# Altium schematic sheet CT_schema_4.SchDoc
size 511 x 398 mm
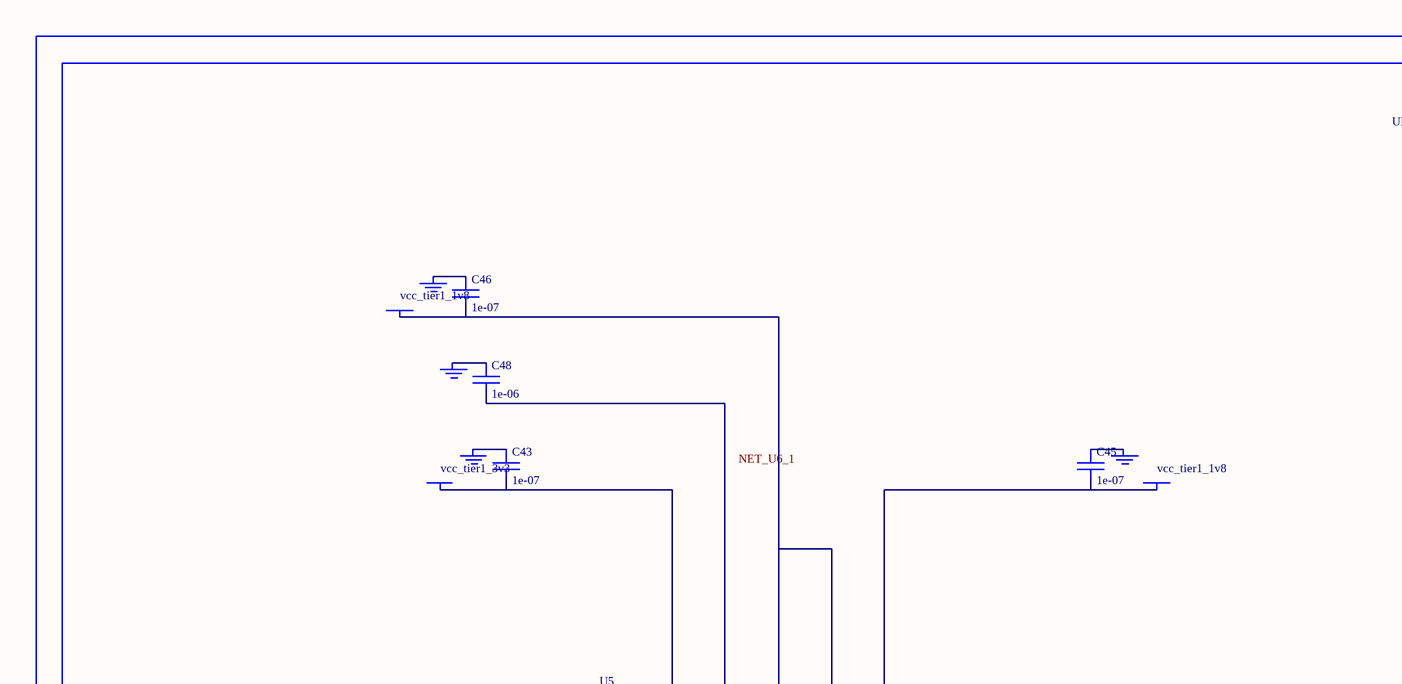
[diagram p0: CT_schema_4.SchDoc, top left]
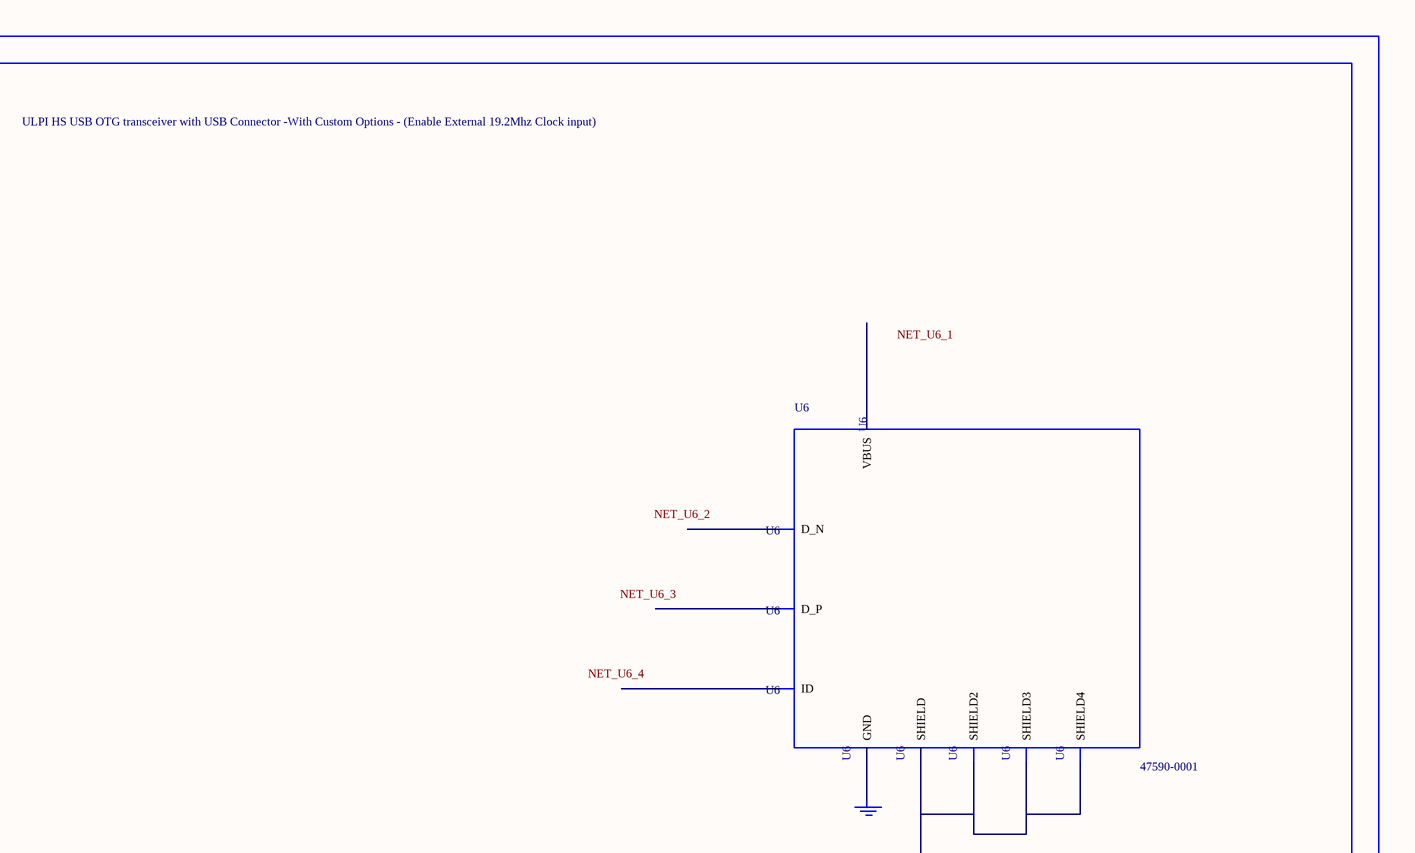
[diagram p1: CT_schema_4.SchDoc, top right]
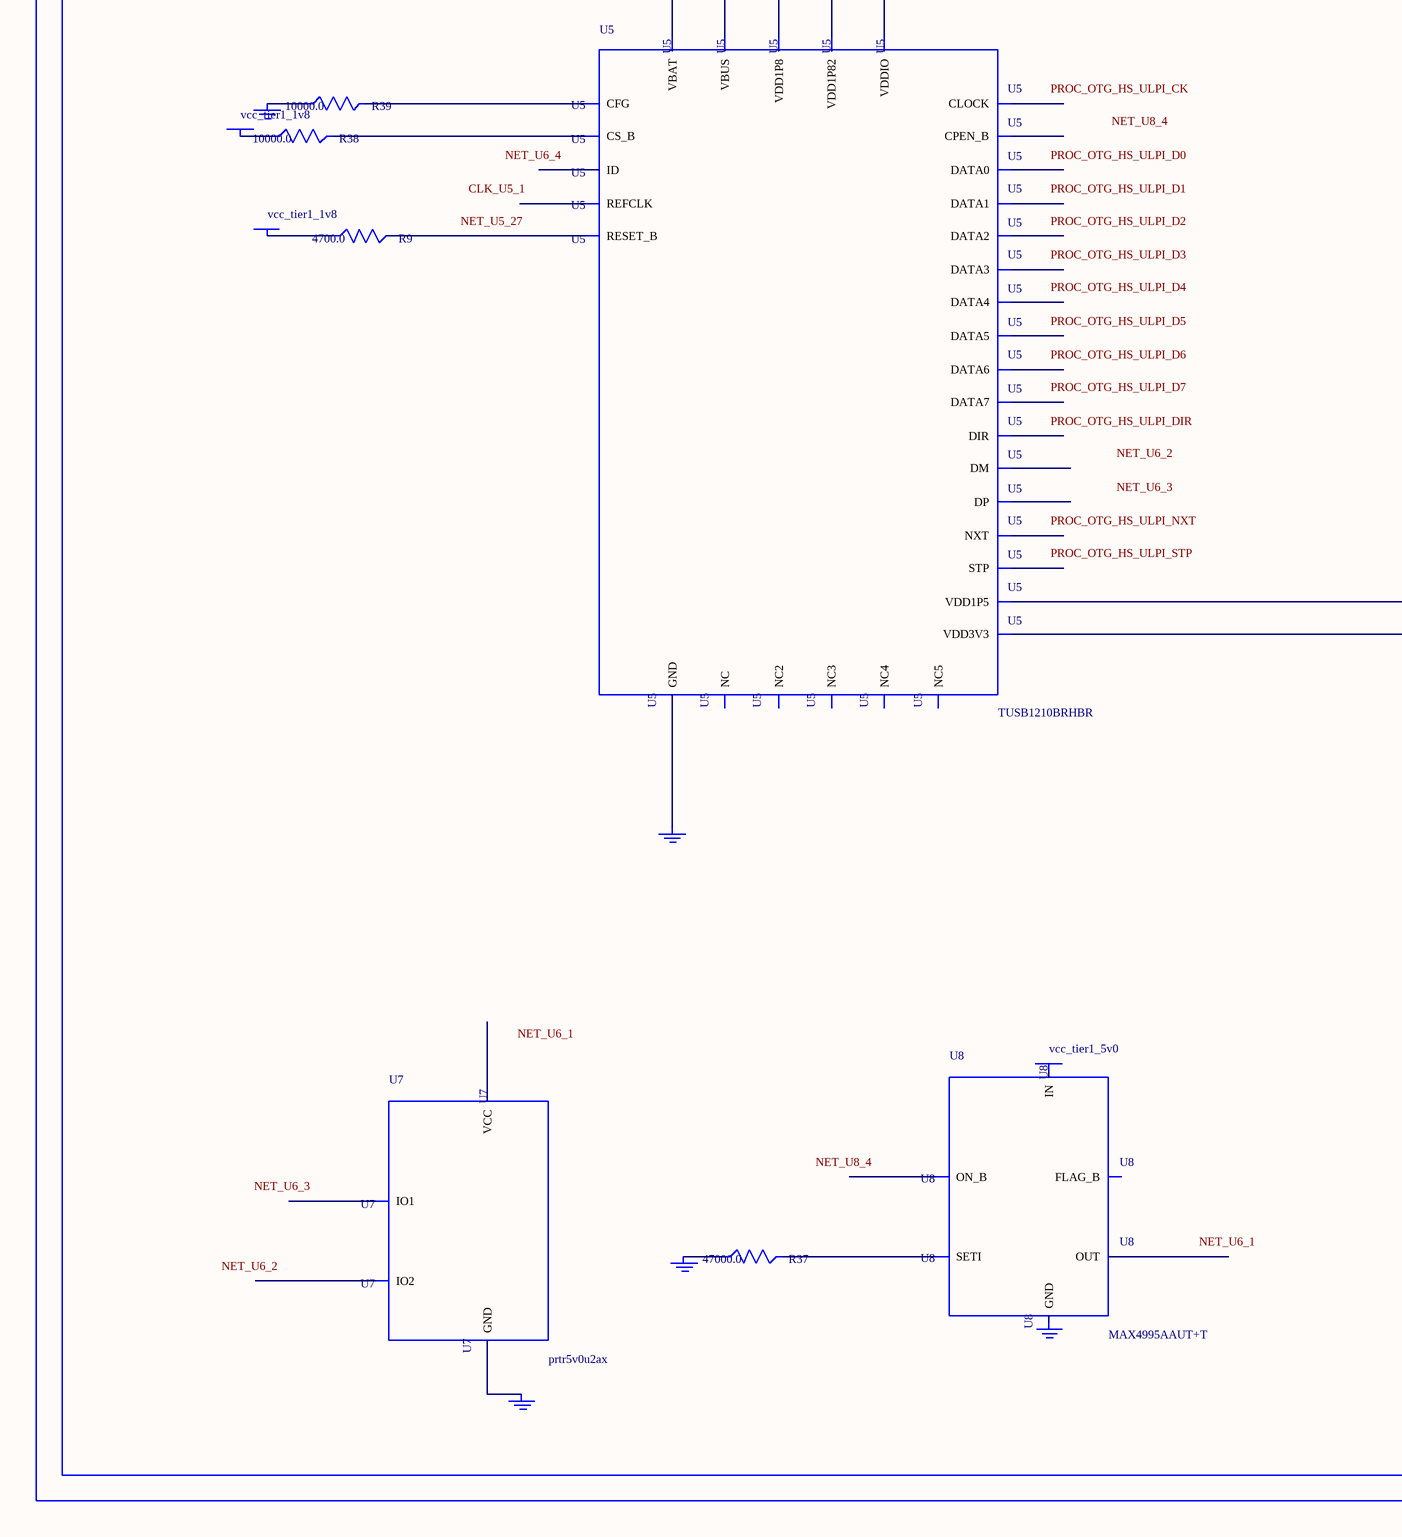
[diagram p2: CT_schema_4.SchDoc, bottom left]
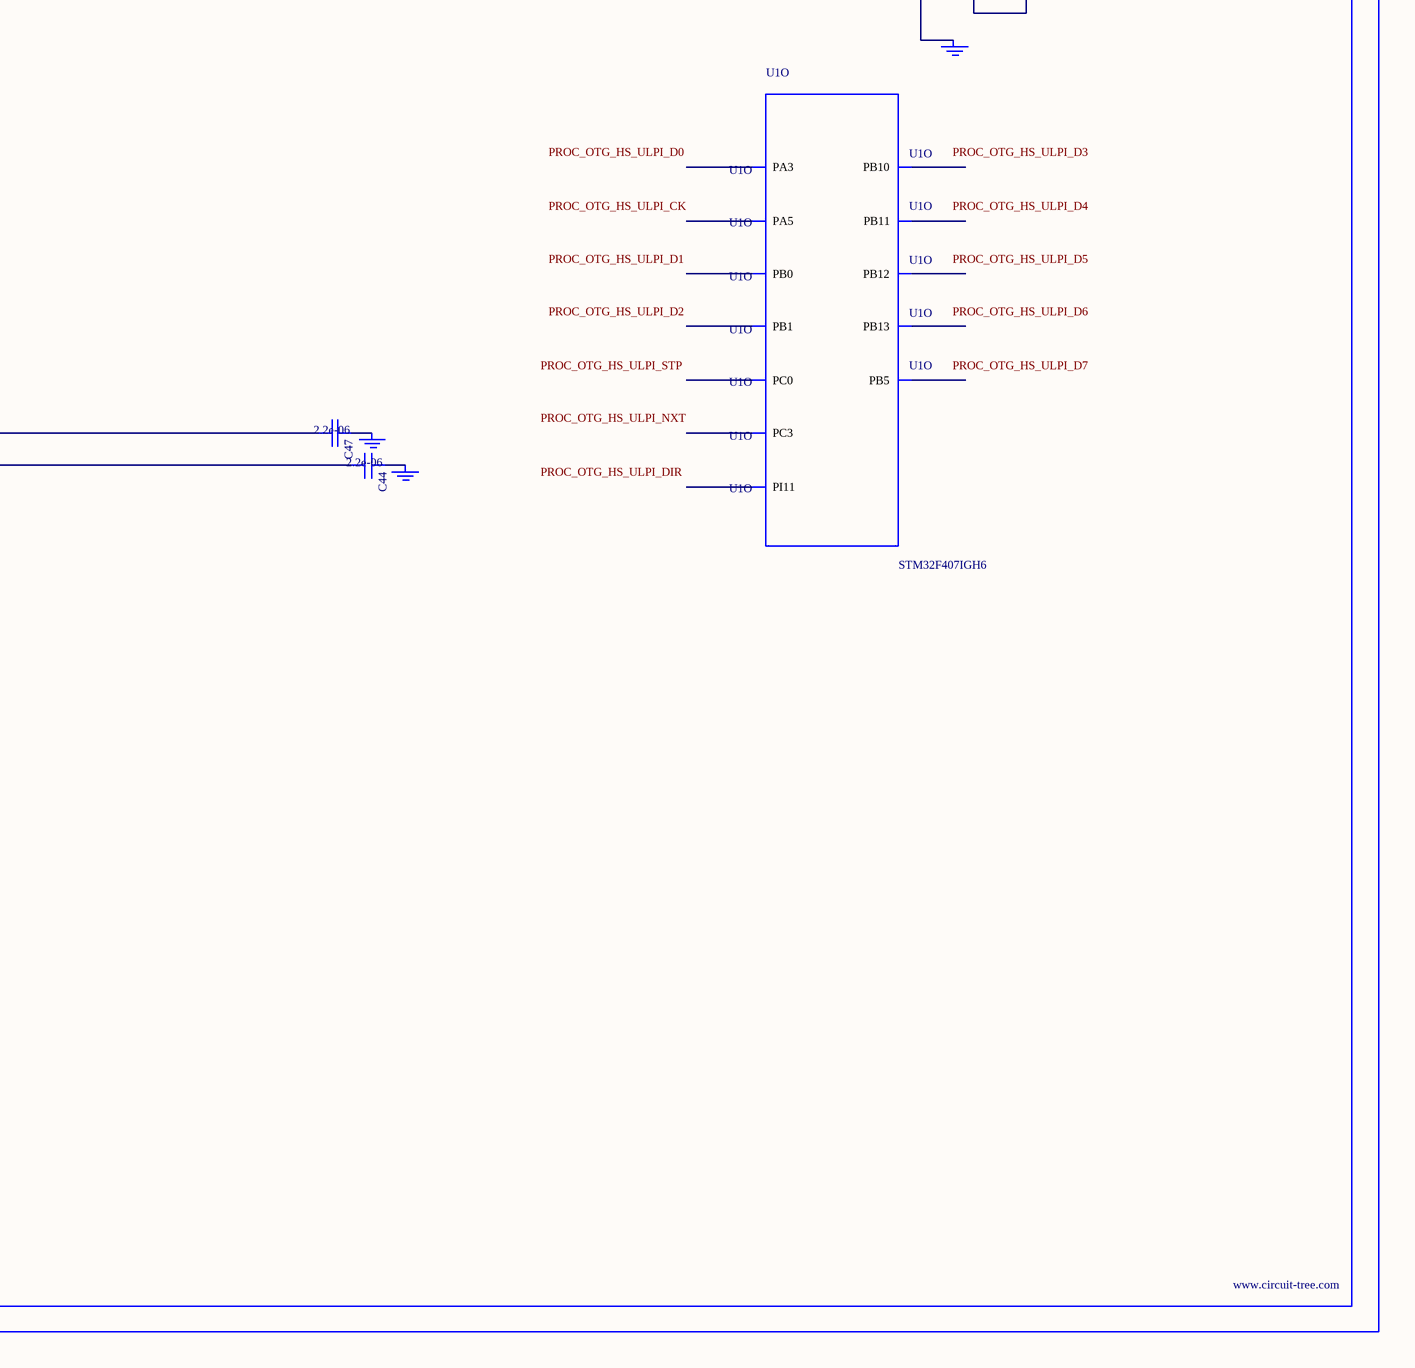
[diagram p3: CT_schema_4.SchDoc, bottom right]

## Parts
BORDER3  (no value)
C43  1e-07  [C0402]
C44  2.2e-06  [C0603]
C45  1e-07  [C0402]
C46  1e-07  [C0402]
C47  2.2e-06  [C0603]
C48  1e-06  [C0603]
GND_INSTANCE_3_0  (no value)
GND_INSTANCE_3_1  (no value)
GND_INSTANCE_3_2  (no value)
GND_INSTANCE_3_3  (no value)
GND_INSTANCE_3_4  (no value)
GND_INSTANCE_3_5  (no value)
GND_INSTANCE_3_6  (no value)
GND_INSTANCE_3_7  (no value)
GND_INSTANCE_3_8  (no value)
GND_INSTANCE_3_9  (no value)
GND_INSTANCE_3_10  (no value)
GND_INSTANCE_3_11  (no value)
GND_INSTANCE_3_12  (no value)
POWER_INSTANCE_3_0  vcc_tier1_1v8
POWER_INSTANCE_3_1  vcc_tier1_3v3
POWER_INSTANCE_3_2  vcc_tier1_1v8
POWER_INSTANCE_3_3  vcc_tier1_1v8
POWER_INSTANCE_3_4  vcc_tier1_1v8
POWER_INSTANCE_3_5  vcc_tier1_5v0
R9  4700.0  [R0603]
R37  47000.0  [R0603]
R38  10000.0  [R0603]
R39  10000.0  [R0603]
U1  STM32F407IGH6  [UFBGA176]  (part O of 15)
U5  TUSB1210BRHBR  [RHB32_3P45X3P45]
U6  47590-0001  [MICRO_USB_AB]
U7  prtr5v0u2ax  [SOT143B]
U8  MAX4995AAUT+T  [SOT-23-6]

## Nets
NetC43_1: C43.1 GND_INSTANCE_3_3.0(GND)
NetC43_2: C43.2 POWER_INSTANCE_3_1.0(PWR) U5.21(VBAT)
NetC44_1: C44.1 GND_INSTANCE_3_2.0(GND)
NetC44_2: C44.2 U5.20(VDD3V3)
NetC45_1: C45.1 GND_INSTANCE_3_6.0(GND)
NetC45_2: C45.2 POWER_INSTANCE_3_3.0(PWR) U5.32(VDDIO)
NetC46_1: C46.1 GND_INSTANCE_3_5.0(GND)
NetC46_2: C46.2 POWER_INSTANCE_3_2.0(PWR) U5.28(VDD1P8) U5.30(VDD1P82)
NetC47_1: C47.1 GND_INSTANCE_3_0.0(GND)
NetC47_2: C47.2 U5.12(VDD1P5)
NetC48_1: C48.1 GND_INSTANCE_3_4.0(GND)
NetC48_2: C48.2 U5.22(VBUS)
NetGND_INSTANCE_3_1_0: GND_INSTANCE_3_1.0(GND) R39.1
NetGND_INSTANCE_3_7_0: GND_INSTANCE_3_7.0(GND) U5.33(GND)
NetGND_INSTANCE_3_8_0: GND_INSTANCE_3_8.0(GND) U6.6(SHIELD) U6.7(SHIELD2) U6.8(SHIELD3) U6.9(SHIELD4)
NetGND_INSTANCE_3_9_0: GND_INSTANCE_3_9.0(GND) U6.5(GND)
NetGND_INSTANCE_3_10_0: GND_INSTANCE_3_10.0(GND) U7.1(GND)
NetGND_INSTANCE_3_11_0: GND_INSTANCE_3_11.0(GND) R37.1
NetPOWER_INSTANCE_3_0_0: POWER_INSTANCE_3_0.0(PWR) R38.1
NetPOWER_INSTANCE_3_4_0: POWER_INSTANCE_3_4.0(PWR) R9.1
NetR9_2: R9.2 U5.27(RESET_B)
NetR37_2: R37.2 U8.3(SETI)
NetR38_2: R38.2 U5.11(CS_B)
NetR39_2: R39.2 U5.14(CFG)

Not connected (* = marked no-connect by the designer): GND_INSTANCE_3_12 0(GND); POWER_INSTANCE_3_5 0(PWR); U1 A6(PB5) E4(PI11) M2(PC0) M5(PC3) P4(PA5) P12(PB12) P13(PB13) R2(PA3) R4(PB1) R5(PB0) R12(PB10) R13(PB11); U5 1(REFCLK) 2(NXT) 3(DATA0) 4(DATA1) 5(DATA2) 6(DATA3) 7(DATA4) 8(NC) 9(DATA5) 10(DATA6) 13(DATA7) 15(NC2) 16(NC3) 17(CPEN_B) 18(DP) 19(DM) 23(ID) 24(NC4) 25(NC5) 26(CLOCK) 29(STP) 31(DIR); U6 1(VBUS) 2(D_N) 3(D_P) 4(ID); U7 2(IO1) 3(IO2) 4(VCC); U8 1(OUT) 2(GND) 4(ON_B) 5(IN) 6(FLAG_B)

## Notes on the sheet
- Labels drawn without touching a wire or pin: CLK_U5_1, NET_U5_27, NET_U6_1, NET_U6_2, NET_U6_3, NET_U6_4, NET_U8_4, PROC_OTG_HS_ULPI_CK, PROC_OTG_HS_ULPI_D0, PROC_OTG_HS_ULPI_D1, PROC_OTG_HS_ULPI_D2, PROC_OTG_HS_ULPI_D3, PROC_OTG_HS_ULPI_D4, PROC_OTG_HS_ULPI_D5, PROC_OTG_HS_ULPI_D6, PROC_OTG_HS_ULPI_D7, PROC_OTG_HS_ULPI_DIR, PROC_OTG_HS_ULPI_NXT, PROC_OTG_HS_ULPI_STP

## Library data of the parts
BORDER3 = BORDER_PAGE3
C43 C45 C46 = C0402C104K3RACTU
C44 C47 = C0603C225K8RACTU
C48 = C0603C105K3RACTU
GND_INSTANCE_3_0-GND_INSTANCE_3_12 = GND
POWER_INSTANCE_3_0-POWER_INSTANCE_3_5 = PWR
R9 = RC0603JR-074K7L
R37 = RC0603JR-0747KL
R38 R39 = RC0603JR-0710KL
